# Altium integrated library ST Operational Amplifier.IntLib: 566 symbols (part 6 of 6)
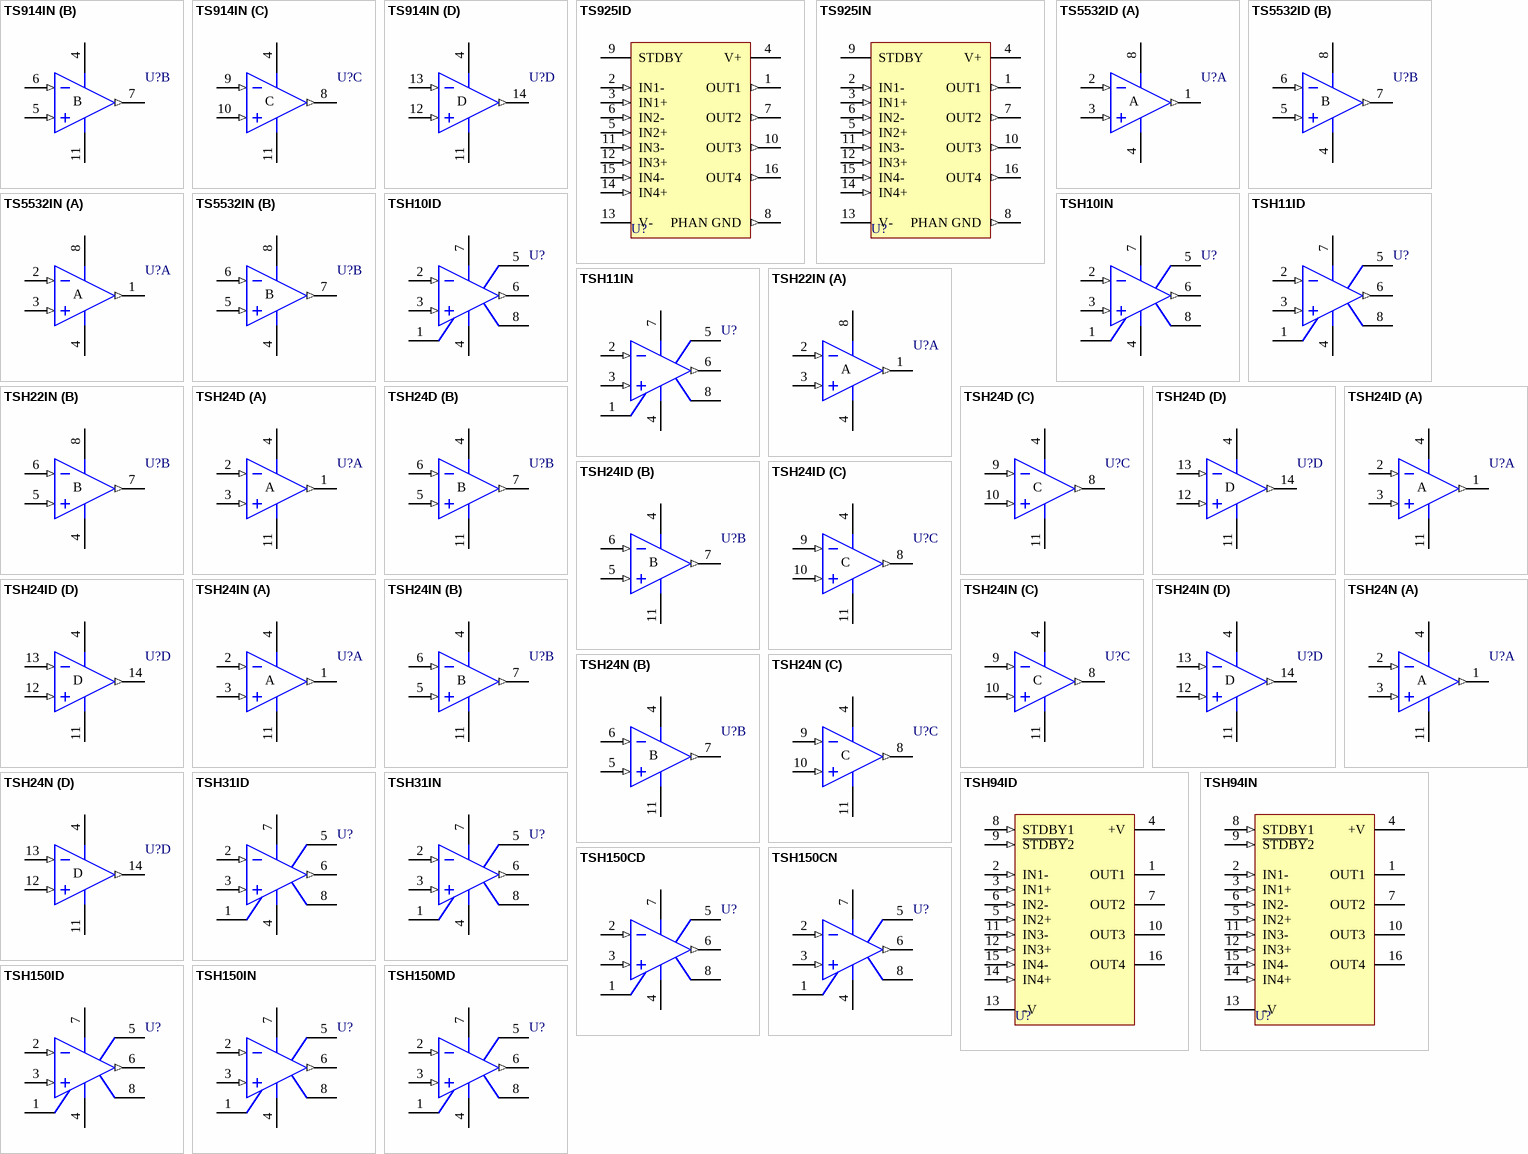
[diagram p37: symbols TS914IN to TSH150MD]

## TS925IN
designator U?
Rail-to-Rail High-Output-Current Quad Operational Amplifier
footprint DIP16 (DIP; 16 Leads; Row Spacing 7.62 mm; Pitch 2.54 mm)
3D model DIP16 (DIP; 16 Leads; Row Spacing 7.62 mm; Pitch 2.54 mm)
pins: 1 OUT1 (out), 2 IN1- (in), 3 IN1+ (in), 4 V+ (power), 5 IN2+ (in), 6 IN2- (in), 7 OUT2 (out), 8 PHAN GND (out), 9 STDBY, 10 OUT3 (out), 11 IN3- (in), 12 IN3+ (in), 13 V- (power), 14 IN4+ (in), 15 IN4- (in), 16 OUT4 (out)

## TS5532ID
designator U?
Low-Noise Dual Operational Amplifier
footprint SO8_N (SOIC, 8-Leads, Body 4.9x3.9mm, Pitch 1.27mm, IPC Medium Density)
footprint SO8_L (SOIC, 8-Leads, Body 4.9x3.9mm, Pitch 1.27mm, IPC High Density)
footprint SO8_M (SOIC, 8-Leads, Body 4.9x3.9mm, Pitch 1.27mm, IPC Low Density)
3D model SO8 (8-Pin Small Outline Integrated Circuit 1.27 mm Pitch)
pins on every part: 4 V- (power), 8 V+ (power)
part A pins: 1 OUT (out), 2 IN- (in), 3 IN+ (in)
part B pins: 5 IN+ (in), 6 IN- (in), 7 OUT (out)

## TS5532IN
designator U?
Low-Noise Dual Operational Amplifier
footprint DIP8 (DIP; 8 Leads; Row Spacing 7.62 mm; Pitch 2.54 mm)
3D model DIP8 (DIP; 8 Leads; Row Spacing 7.62 mm; Pitch 2.54 mm)
pins on every part: 4 V- (power), 8 V+ (power)
part A pins: 1 OUT (out), 2 IN- (in), 3 IN+ (in)
part B pins: 5 IN+ (in), 6 IN- (in), 7 OUT (out)

## TSH10ID
designator U?
140MHz Bandwidth Low-Noise Operational Amplifier; Note: Pins 5 is Not Connected
footprint SO8_N (SOIC, 8-Leads, Body 4.9x3.9mm, Pitch 1.27mm, IPC Medium Density)
footprint SO8_L (SOIC, 8-Leads, Body 4.9x3.9mm, Pitch 1.27mm, IPC High Density)
footprint SO8_M (SOIC, 8-Leads, Body 4.9x3.9mm, Pitch 1.27mm, IPC Low Density)
3D model SO8 (8-Pin Small Outline Integrated Circuit 1.27 mm Pitch)
pins: 1 NULL1, 2 IN- (in), 3 IN+ (in), 4 V- (power), 5 NC, 6 OUT (out), 7 V+ (power), 8 NULL2

## TSH10IN
designator U?
140MHz Bandwidth Low-Noise Operational Amplifier; Note: Pins 5 is Not Connected
footprint DIP8 (DIP; 8 Leads; Row Spacing 7.62 mm; Pitch 2.54 mm)
3D model DIP8 (DIP; 8 Leads; Row Spacing 7.62 mm; Pitch 2.54 mm)
pins: 1 NULL1, 2 IN- (in), 3 IN+ (in), 4 V- (power), 5 NC, 6 OUT (out), 7 V+ (power), 8 NULL2

## TSH11ID
designator U?
120MHz Bandwidth MOS Input Single Operational Amplifier; Note: Pins 5 is Not Connected
footprint SO8_N (SOIC, 8-Leads, Body 4.9x3.9mm, Pitch 1.27mm, IPC Medium Density)
footprint SO8_L (SOIC, 8-Leads, Body 4.9x3.9mm, Pitch 1.27mm, IPC High Density)
footprint SO8_M (SOIC, 8-Leads, Body 4.9x3.9mm, Pitch 1.27mm, IPC Low Density)
3D model SO8 (8-Pin Small Outline Integrated Circuit 1.27 mm Pitch)
pins: 1 NULL1, 2 IN- (in), 3 IN+ (in), 4 V- (power), 5 NC, 6 OUT (out), 7 V+ (power), 8 NULL2

## TSH11IN
designator U?
120MHz Bandwidth MOS Input Single Operational Amplifier; Note: Pins 5 is Not Connected
footprint DIP8 (DIP; 8 Leads; Row Spacing 7.62 mm; Pitch 2.54 mm)
3D model DIP8 (DIP; 8 Leads; Row Spacing 7.62 mm; Pitch 2.54 mm)
pins: 1 NULL1, 2 IN- (in), 3 IN+ (in), 4 V- (power), 5 NC, 6 OUT (out), 7 V+ (power), 8 NULL2

## TSH22IN
designator U?
High-Performance Dual Bipolar Operational Amplifier
footprint DIP8 (DIP; 8 Leads; Row Spacing 7.62 mm; Pitch 2.54 mm)
3D model DIP8 (DIP; 8 Leads; Row Spacing 7.62 mm; Pitch 2.54 mm)
pins on every part: 4 V- (power), 8 V+ (power)
part A pins: 1 OUT (out), 2 IN- (in), 3 IN+ (in)
part B pins: 5 IN+ (in), 6 IN- (in), 7 OUT (out)

## TSH24D
designator U?
High-Performance Quad Bipolar Operational Amplifier
footprint SO14_N (SOIC, 14-Leads, Body 8.7x3.9mm, Pitch 1.27mm, IPC Medium Density)
footprint SO14_L (SOIC, 14-Leads, Body 8.7x3.9mm, Pitch 1.27mm, IPC High Density)
footprint SO14_M (SOIC, 14-Leads, Body 8.7x3.9mm, Pitch 1.27mm, IPC Low Density)
3D model SO14 (14-Pin Small Outline Integrated Circuit 1.27 mm Pitch)
pins on every part: 4 V+ (power), 11 V- (power)
part A pins: 1 OUT (out), 2 IN- (in), 3 IN+ (in)
part B pins: 5 IN+ (in), 6 IN- (in), 7 OUT (out)
part C pins: 8 OUT (out), 9 IN- (in), 10 IN+ (in)
part D pins: 12 IN+ (in), 13 IN- (in), 14 OUT (out)

## TSH24ID
designator U?
High-Performance Quad Bipolar Operational Amplifier
footprint SO14_N (SOIC, 14-Leads, Body 8.7x3.9mm, Pitch 1.27mm, IPC Medium Density)
footprint SO14_L (SOIC, 14-Leads, Body 8.7x3.9mm, Pitch 1.27mm, IPC High Density)
footprint SO14_M (SOIC, 14-Leads, Body 8.7x3.9mm, Pitch 1.27mm, IPC Low Density)
3D model SO14 (14-Pin Small Outline Integrated Circuit 1.27 mm Pitch)
pins on every part: 4 V+ (power), 11 V- (power)
part A pins: 1 OUT (out), 2 IN- (in), 3 IN+ (in)
part B pins: 5 IN+ (in), 6 IN- (in), 7 OUT (out)
part C pins: 8 OUT (out), 9 IN- (in), 10 IN+ (in)
part D pins: 12 IN+ (in), 13 IN- (in), 14 OUT (out)

## TSH24IN
designator U?
High-Performance Quad Bipolar Operational Amplifier
footprint DIP14 (DIP; 14 Leads; Row Spacing 7.62 mm; Pitch 2.54 mm)
3D model DIP14 (DIP; 14 Leads; Row Spacing 7.62 mm; Pitch 2.54 mm)
pins on every part: 4 V+ (power), 11 V- (power)
part A pins: 1 OUT (out), 2 IN- (in), 3 IN+ (in)
part B pins: 5 IN+ (in), 6 IN- (in), 7 OUT (out)
part C pins: 8 OUT (out), 9 IN- (in), 10 IN+ (in)
part D pins: 12 IN+ (in), 13 IN- (in), 14 OUT (out)

## TSH24N
designator U?
High-Performance Quad Bipolar Operational Amplifier
footprint DIP14 (DIP; 14 Leads; Row Spacing 7.62 mm; Pitch 2.54 mm)
3D model DIP14 (DIP; 14 Leads; Row Spacing 7.62 mm; Pitch 2.54 mm)
pins on every part: 4 V+ (power), 11 V- (power)
part A pins: 1 OUT (out), 2 IN- (in), 3 IN+ (in)
part B pins: 5 IN+ (in), 6 IN- (in), 7 OUT (out)
part C pins: 8 OUT (out), 9 IN- (in), 10 IN+ (in)
part D pins: 12 IN+ (in), 13 IN- (in), 14 OUT (out)

## TSH31ID
designator U?
280MHz Bandwidth MOS Input Single Operational Amplifier; Note: Pins 5 is Not Connected
footprint SO8_N (SOIC, 8-Leads, Body 4.9x3.9mm, Pitch 1.27mm, IPC Medium Density)
footprint SO8_L (SOIC, 8-Leads, Body 4.9x3.9mm, Pitch 1.27mm, IPC High Density)
footprint SO8_M (SOIC, 8-Leads, Body 4.9x3.9mm, Pitch 1.27mm, IPC Low Density)
3D model SO8 (8-Pin Small Outline Integrated Circuit 1.27 mm Pitch)
pins: 1 NULL1, 2 IN- (in), 3 IN+ (in), 4 V- (power), 5 NC, 6 OUT (out), 7 V+ (power), 8 NULL2

## TSH31IN
designator U?
280MHz Bandwidth MOS Input Single Operational Amplifier; Note: Pins 5 is Not Connected
footprint DIP8 (DIP; 8 Leads; Row Spacing 7.62 mm; Pitch 2.54 mm)
3D model DIP8 (DIP; 8 Leads; Row Spacing 7.62 mm; Pitch 2.54 mm)
pins: 1 NULL1, 2 IN- (in), 3 IN+ (in), 4 V- (power), 5 NC, 6 OUT (out), 7 V+ (power), 8 NULL2

## TSH94ID
designator U?
High-Speed Low-Power Quad Operational Amplifier (with Standby Position)
footprint SO16_N (SOIC, 16-Leads, Body 9.9x3.9mm, Pitch 1.27mm, IPC Medium Density)
footprint SO16_L (SOIC, 16-Leads, Body 9.9x3.9mm, Pitch 1.27mm, IPC High Density)
footprint SO16_M (SOIC, 16-Leads, Body 9.9x3.9mm, Pitch 1.27mm, IPC Low Density)
3D model SO16 (16-Pin Small Outline Integrated Circuit 1.27 mm Pitch)
pins: 1 OUT1 (hiz), 2 IN1- (in), 3 IN1+ (in), 4 +V (power), 5 IN2+ (in), 6 IN2- (in), 7 OUT2 (hiz), 8 STDBY1 (in), 9 ~{STDBY}2 (in), 10 OUT3 (hiz), 11 IN3- (in), 12 IN3+ (in), 13 -V (power), 14 IN4+ (in), 15 IN4- (in), 16 OUT4 (hiz)

## TSH94IN
designator U?
High-Speed Low-Power Quad Operational Amplifier (with Standby Position)
footprint DIP16 (DIP; 16 Leads; Row Spacing 7.62 mm; Pitch 2.54 mm)
3D model DIP16 (DIP; 16 Leads; Row Spacing 7.62 mm; Pitch 2.54 mm)
pins: 1 OUT1 (hiz), 2 IN1- (in), 3 IN1+ (in), 4 +V (power), 5 IN2+ (in), 6 IN2- (in), 7 OUT2 (hiz), 8 STDBY1 (in), 9 ~{STDBY}2 (in), 10 OUT3 (hiz), 11 IN3- (in), 12 IN3+ (in), 13 -V (power), 14 IN4+ (in), 15 IN4- (in), 16 OUT4 (hiz)

## TSH150CD
designator U?
Wide-Bandwidth and Bipolar Inputs Single Operational Amplifier; Note: Pins 5 is Not Connected
footprint SO8_N (SOIC, 8-Leads, Body 4.9x3.9mm, Pitch 1.27mm, IPC Medium Density)
footprint SO8_L (SOIC, 8-Leads, Body 4.9x3.9mm, Pitch 1.27mm, IPC High Density)
footprint SO8_M (SOIC, 8-Leads, Body 4.9x3.9mm, Pitch 1.27mm, IPC Low Density)
3D model SO8 (8-Pin Small Outline Integrated Circuit 1.27 mm Pitch)
pins: 1 NULL1, 2 IN- (in), 3 IN+ (in), 4 V- (power), 5 NC, 6 OUT (out), 7 V+ (power), 8 NULL2

## TSH150CN
designator U?
Wide-Bandwidth and Bipolar Inputs Single Operational Amplifier; Note: Pins 5 is Not Connected
footprint DIP8 (DIP; 8 Leads; Row Spacing 7.62 mm; Pitch 2.54 mm)
3D model DIP8 (DIP; 8 Leads; Row Spacing 7.62 mm; Pitch 2.54 mm)
pins: 1 NULL1, 2 IN- (in), 3 IN+ (in), 4 V- (power), 5 NC, 6 OUT (out), 7 V+ (power), 8 NULL2

## TSH150ID
designator U?
Wide-Bandwidth and Bipolar Inputs Single Operational Amplifier; Note: Pins 5 is Not Connected
footprint SO8_N (SOIC, 8-Leads, Body 4.9x3.9mm, Pitch 1.27mm, IPC Medium Density)
footprint SO8_L (SOIC, 8-Leads, Body 4.9x3.9mm, Pitch 1.27mm, IPC High Density)
footprint SO8_M (SOIC, 8-Leads, Body 4.9x3.9mm, Pitch 1.27mm, IPC Low Density)
3D model SO8 (8-Pin Small Outline Integrated Circuit 1.27 mm Pitch)
pins: 1 NULL1, 2 IN- (in), 3 IN+ (in), 4 V- (power), 5 NC, 6 OUT (out), 7 V+ (power), 8 NULL2

## TSH150IN
designator U?
Wide-Bandwidth and Bipolar Inputs Single Operational Amplifier; Note: Pins 5 is Not Connected
footprint DIP8 (DIP; 8 Leads; Row Spacing 7.62 mm; Pitch 2.54 mm)
3D model DIP8 (DIP; 8 Leads; Row Spacing 7.62 mm; Pitch 2.54 mm)
pins: 1 NULL1, 2 IN- (in), 3 IN+ (in), 4 V- (power), 5 NC, 6 OUT (out), 7 V+ (power), 8 NULL2

## TSH150MD
designator U?
Wide-Bandwidth and Bipolar Inputs Single Operational Amplifier; Note: Pins 5 is Not Connected
footprint SO8_N (SOIC, 8-Leads, Body 4.9x3.9mm, Pitch 1.27mm, IPC Medium Density)
footprint SO8_L (SOIC, 8-Leads, Body 4.9x3.9mm, Pitch 1.27mm, IPC High Density)
footprint SO8_M (SOIC, 8-Leads, Body 4.9x3.9mm, Pitch 1.27mm, IPC Low Density)
3D model SO8 (8-Pin Small Outline Integrated Circuit 1.27 mm Pitch)
pins: 1 NULL1, 2 IN- (in), 3 IN+ (in), 4 V- (power), 5 NC, 6 OUT (out), 7 V+ (power), 8 NULL2

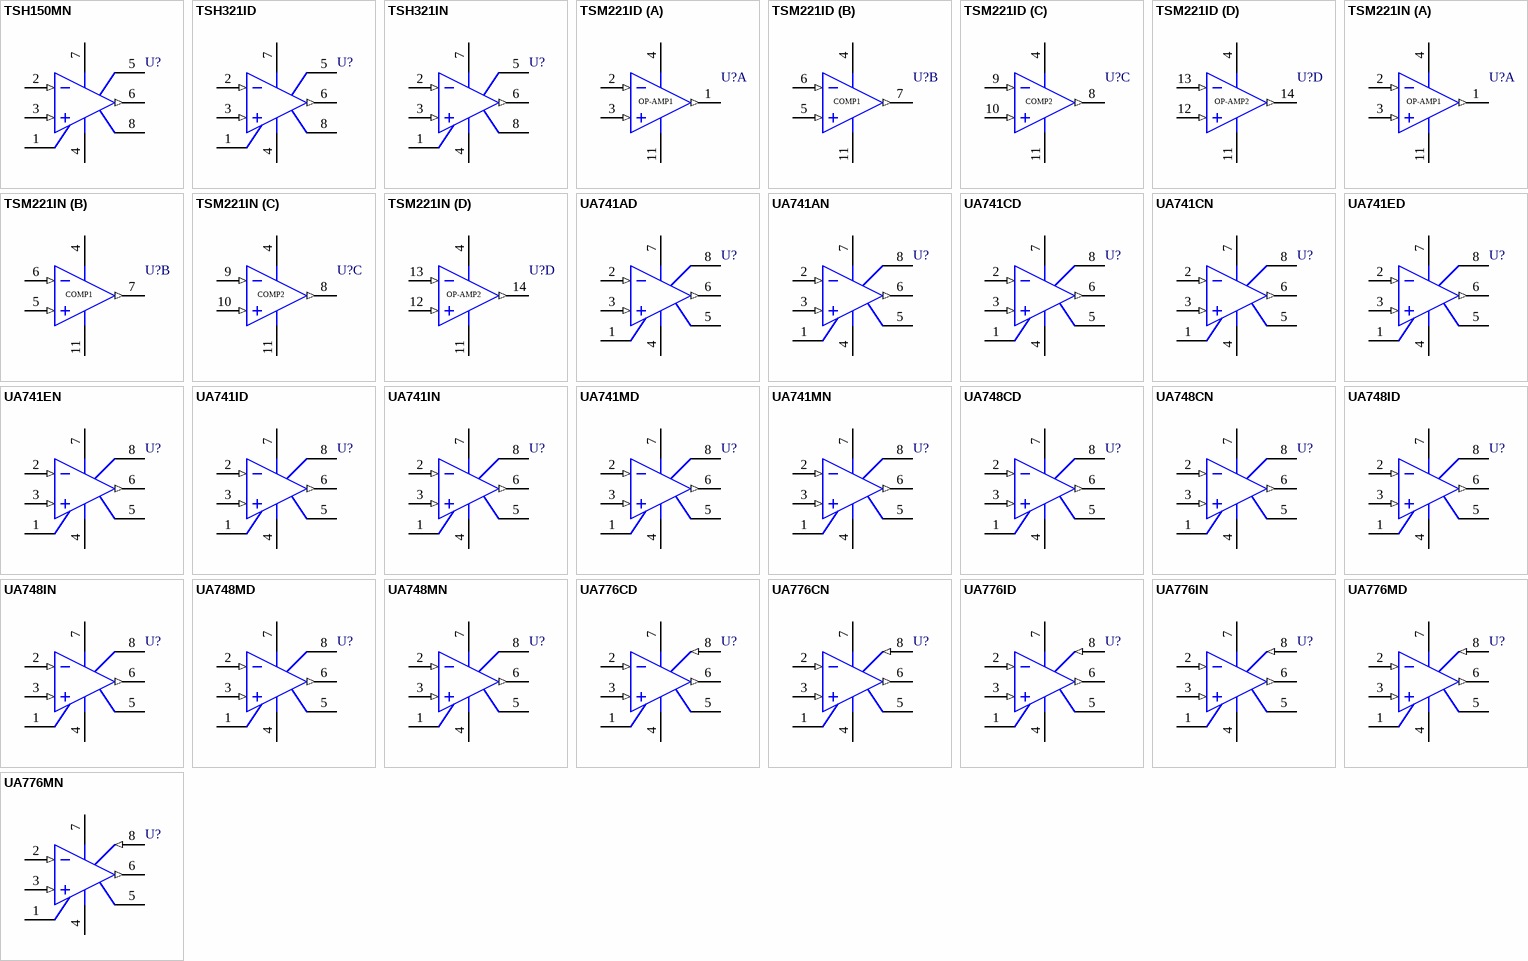
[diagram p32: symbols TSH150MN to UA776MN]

## TSH150MN
designator U?
Wide-Bandwidth and Bipolar Inputs Single Operational Amplifier; Note: Pins 5 is Not Connected
footprint DIP8 (DIP; 8 Leads; Row Spacing 7.62 mm; Pitch 2.54 mm)
3D model DIP8 (DIP; 8 Leads; Row Spacing 7.62 mm; Pitch 2.54 mm)
pins: 1 NULL1, 2 IN- (in), 3 IN+ (in), 4 V- (power), 5 NC, 6 OUT (out), 7 V+ (power), 8 NULL2

## TSH321ID
designator U?
Wide-Bandwidth and MOS Inputs Single Operational Amplifier; Note: Pins 5 is Not Connected
footprint SO8_N (SOIC, 8-Leads, Body 4.9x3.9mm, Pitch 1.27mm, IPC Medium Density)
footprint SO8_L (SOIC, 8-Leads, Body 4.9x3.9mm, Pitch 1.27mm, IPC High Density)
footprint SO8_M (SOIC, 8-Leads, Body 4.9x3.9mm, Pitch 1.27mm, IPC Low Density)
3D model SO8 (8-Pin Small Outline Integrated Circuit 1.27 mm Pitch)
pins: 1 NULL1, 2 IN- (in), 3 IN+ (in), 4 V- (power), 5 NC, 6 OUT (out), 7 V+ (power), 8 NULL2

## TSH321IN
designator U?
Wide-Bandwidth and MOS Inputs Single Operational Amplifier; Note: Pins 5 is Not Connected
footprint DIP8 (DIP; 8 Leads; Row Spacing 7.62 mm; Pitch 2.54 mm)
3D model DIP8 (DIP; 8 Leads; Row Spacing 7.62 mm; Pitch 2.54 mm)
pins: 1 NULL1, 2 IN- (in), 3 IN+ (in), 4 V- (power), 5 NC, 6 OUT (out), 7 V+ (power), 8 NULL2

## TSM221ID
designator U?
Dual CMOS Rail-to-Rail Operational Amplifier and Dual CMOS Comparator; ComponentAvailability: Not for New Design
footprint SO14_N (SOIC, 14-Leads, Body 8.7x3.9mm, Pitch 1.27mm, IPC Medium Density)
footprint SO14_L (SOIC, 14-Leads, Body 8.7x3.9mm, Pitch 1.27mm, IPC High Density)
footprint SO14_M (SOIC, 14-Leads, Body 8.7x3.9mm, Pitch 1.27mm, IPC Low Density)
3D model SO14 (14-Pin Small Outline Integrated Circuit 1.27 mm Pitch)
pins on every part: 4 V+ (power), 11 V- (power)
part A pins: 1 OUT (out), 2 IN- (in), 3 IN+ (in)
part B pins: 5 IN+ (in), 6 IN- (in), 7 OUT (out)
part C pins: 8 OUT (out), 9 IN- (in), 10 IN+ (in)
part D pins: 12 IN+ (in), 13 IN- (in), 14 OUT (out)

## TSM221IN
designator U?
Dual CMOS Rail-to-Rail Operational Amplifier and Dual CMOS Comparator; ComponentAvailability: Not for New Design
footprint DIP14 (DIP; 14 Leads; Row Spacing 7.62 mm; Pitch 2.54 mm)
3D model DIP14 (DIP; 14 Leads; Row Spacing 7.62 mm; Pitch 2.54 mm)
pins on every part: 4 V+ (power), 11 V- (power)
part A pins: 1 OUT (out), 2 IN- (in), 3 IN+ (in)
part B pins: 5 IN+ (in), 6 IN- (in), 7 OUT (out)
part C pins: 8 OUT (out), 9 IN- (in), 10 IN+ (in)
part D pins: 12 IN+ (in), 13 IN- (in), 14 OUT (out)

## UA741AD
designator U?
General-Purpose Single Operational Amplifier
footprint SO8_N (SOIC, 8-Leads, Body 4.9x3.9mm, Pitch 1.27mm, IPC Medium Density)
footprint SO8_L (SOIC, 8-Leads, Body 4.9x3.9mm, Pitch 1.27mm, IPC High Density)
footprint SO8_M (SOIC, 8-Leads, Body 4.9x3.9mm, Pitch 1.27mm, IPC Low Density)
3D model SO8 (8-Pin Small Outline Integrated Circuit 1.27 mm Pitch)
simulation model UA741 (SUBCKT)
pins: 1 OS NULL, 2 IN- (in), 3 IN+ (in), 4 V- (power), 5 OS NULL, 6 OUT (out), 7 V+ (power), 8 NC

## UA741AN
designator U?
General-Purpose Single Operational Amplifier
footprint DIP8 (DIP; 8 Leads; Row Spacing 7.62 mm; Pitch 2.54 mm)
3D model DIP8 (DIP; 8 Leads; Row Spacing 7.62 mm; Pitch 2.54 mm)
simulation model UA741 (SUBCKT)
pins: 1 OS NULL, 2 IN- (in), 3 IN+ (in), 4 V- (power), 5 OS NULL, 6 OUT (out), 7 V+ (power), 8 NC

## UA741CD
designator U?
General-Purpose Single Operational Amplifier
footprint SO8_N (SOIC, 8-Leads, Body 4.9x3.9mm, Pitch 1.27mm, IPC Medium Density)
footprint SO8_L (SOIC, 8-Leads, Body 4.9x3.9mm, Pitch 1.27mm, IPC High Density)
footprint SO8_M (SOIC, 8-Leads, Body 4.9x3.9mm, Pitch 1.27mm, IPC Low Density)
3D model SO8 (8-Pin Small Outline Integrated Circuit 1.27 mm Pitch)
simulation model UA741 (SUBCKT)
pins: 1 OS NULL, 2 IN- (in), 3 IN+ (in), 4 V- (power), 5 OS NULL, 6 OUT (out), 7 V+ (power), 8 NC

## UA741CN
designator U?
General-Purpose Single Operational Amplifier
footprint DIP8 (DIP; 8 Leads; Row Spacing 7.62 mm; Pitch 2.54 mm)
3D model DIP8 (DIP; 8 Leads; Row Spacing 7.62 mm; Pitch 2.54 mm)
simulation model UA741 (SUBCKT)
pins: 1 OS NULL, 2 IN- (in), 3 IN+ (in), 4 V- (power), 5 OS NULL, 6 OUT (out), 7 V+ (power), 8 NC

## UA741ED
designator U?
General-Purpose Single Operational Amplifier
footprint SO8_N (SOIC, 8-Leads, Body 4.9x3.9mm, Pitch 1.27mm, IPC Medium Density)
footprint SO8_L (SOIC, 8-Leads, Body 4.9x3.9mm, Pitch 1.27mm, IPC High Density)
footprint SO8_M (SOIC, 8-Leads, Body 4.9x3.9mm, Pitch 1.27mm, IPC Low Density)
3D model SO8 (8-Pin Small Outline Integrated Circuit 1.27 mm Pitch)
simulation model UA741 (SUBCKT)
pins: 1 OS NULL, 2 IN- (in), 3 IN+ (in), 4 V- (power), 5 OS NULL, 6 OUT (out), 7 V+ (power), 8 NC

## UA741EN
designator U?
General-Purpose Single Operational Amplifier
footprint DIP8 (DIP; 8 Leads; Row Spacing 7.62 mm; Pitch 2.54 mm)
3D model DIP8 (DIP; 8 Leads; Row Spacing 7.62 mm; Pitch 2.54 mm)
simulation model UA741 (SUBCKT)
pins: 1 OS NULL, 2 IN- (in), 3 IN+ (in), 4 V- (power), 5 OS NULL, 6 OUT (out), 7 V+ (power), 8 NC

## UA741ID
designator U?
General-Purpose Single Operational Amplifier
footprint SO8_N (SOIC, 8-Leads, Body 4.9x3.9mm, Pitch 1.27mm, IPC Medium Density)
footprint SO8_L (SOIC, 8-Leads, Body 4.9x3.9mm, Pitch 1.27mm, IPC High Density)
footprint SO8_M (SOIC, 8-Leads, Body 4.9x3.9mm, Pitch 1.27mm, IPC Low Density)
3D model SO8 (8-Pin Small Outline Integrated Circuit 1.27 mm Pitch)
simulation model UA741 (SUBCKT)
pins: 1 OS NULL, 2 IN- (in), 3 IN+ (in), 4 V- (power), 5 OS NULL, 6 OUT (out), 7 V+ (power), 8 NC

## UA741IN
designator U?
General-Purpose Single Operational Amplifier
footprint DIP8 (DIP; 8 Leads; Row Spacing 7.62 mm; Pitch 2.54 mm)
3D model DIP8 (DIP; 8 Leads; Row Spacing 7.62 mm; Pitch 2.54 mm)
simulation model UA741 (SUBCKT)
pins: 1 OS NULL, 2 IN- (in), 3 IN+ (in), 4 V- (power), 5 OS NULL, 6 OUT (out), 7 V+ (power), 8 NC

## UA741MD
designator U?
General-Purpose Single Operational Amplifier
footprint SO8_N (SOIC, 8-Leads, Body 4.9x3.9mm, Pitch 1.27mm, IPC Medium Density)
footprint SO8_L (SOIC, 8-Leads, Body 4.9x3.9mm, Pitch 1.27mm, IPC High Density)
footprint SO8_M (SOIC, 8-Leads, Body 4.9x3.9mm, Pitch 1.27mm, IPC Low Density)
3D model SO8 (8-Pin Small Outline Integrated Circuit 1.27 mm Pitch)
simulation model UA741 (SUBCKT)
pins: 1 OS NULL, 2 IN- (in), 3 IN+ (in), 4 V- (power), 5 OS NULL, 6 OUT (out), 7 V+ (power), 8 NC

## UA741MN
designator U?
General-Purpose Single Operational Amplifier
footprint DIP8 (DIP; 8 Leads; Row Spacing 7.62 mm; Pitch 2.54 mm)
3D model DIP8 (DIP; 8 Leads; Row Spacing 7.62 mm; Pitch 2.54 mm)
simulation model UA741 (SUBCKT)
pins: 1 OS NULL, 2 IN- (in), 3 IN+ (in), 4 V- (power), 5 OS NULL, 6 OUT (out), 7 V+ (power), 8 NC

## UA748CD
designator U?
Precision Single Operational Amplifier
footprint SO8_N (SOIC, 8-Leads, Body 4.9x3.9mm, Pitch 1.27mm, IPC Medium Density)
footprint SO8_L (SOIC, 8-Leads, Body 4.9x3.9mm, Pitch 1.27mm, IPC High Density)
footprint SO8_M (SOIC, 8-Leads, Body 4.9x3.9mm, Pitch 1.27mm, IPC Low Density)
3D model SO8 (8-Pin Small Outline Integrated Circuit 1.27 mm Pitch)
simulation model UA748 (SUBCKT)
pins: 1 OS NULL1/FCOMP, 2 IN- (in), 3 IN+ (in), 4 V- (power), 5 OS NULL2, 6 OUT (out), 7 V+ (power), 8 FCOMP

## UA748CN
designator U?
Precision Single Operational Amplifier
footprint DIP8 (DIP; 8 Leads; Row Spacing 7.62 mm; Pitch 2.54 mm)
3D model DIP8 (DIP; 8 Leads; Row Spacing 7.62 mm; Pitch 2.54 mm)
simulation model UA748 (SUBCKT)
pins: 1 OS NULL1/FCOMP, 2 IN- (in), 3 IN+ (in), 4 V- (power), 5 OS NULL2, 6 OUT (out), 7 V+ (power), 8 FCOMP

## UA748ID
designator U?
Precision Single Operational Amplifier
footprint SO8_N (SOIC, 8-Leads, Body 4.9x3.9mm, Pitch 1.27mm, IPC Medium Density)
footprint SO8_L (SOIC, 8-Leads, Body 4.9x3.9mm, Pitch 1.27mm, IPC High Density)
footprint SO8_M (SOIC, 8-Leads, Body 4.9x3.9mm, Pitch 1.27mm, IPC Low Density)
3D model SO8 (8-Pin Small Outline Integrated Circuit 1.27 mm Pitch)
simulation model UA748 (SUBCKT)
pins: 1 OS NULL1/FCOMP, 2 IN- (in), 3 IN+ (in), 4 V- (power), 5 OS NULL2, 6 OUT (out), 7 V+ (power), 8 FCOMP

## UA748IN
designator U?
Precision Single Operational Amplifier
footprint DIP8 (DIP; 8 Leads; Row Spacing 7.62 mm; Pitch 2.54 mm)
3D model DIP8 (DIP; 8 Leads; Row Spacing 7.62 mm; Pitch 2.54 mm)
simulation model UA748 (SUBCKT)
pins: 1 OS NULL1/FCOMP, 2 IN- (in), 3 IN+ (in), 4 V- (power), 5 OS NULL2, 6 OUT (out), 7 V+ (power), 8 FCOMP

## UA748MD
designator U?
Precision Single Operational Amplifier
footprint SO8_N (SOIC, 8-Leads, Body 4.9x3.9mm, Pitch 1.27mm, IPC Medium Density)
footprint SO8_L (SOIC, 8-Leads, Body 4.9x3.9mm, Pitch 1.27mm, IPC High Density)
footprint SO8_M (SOIC, 8-Leads, Body 4.9x3.9mm, Pitch 1.27mm, IPC Low Density)
3D model SO8 (8-Pin Small Outline Integrated Circuit 1.27 mm Pitch)
simulation model UA748 (SUBCKT)
pins: 1 OS NULL1/FCOMP, 2 IN- (in), 3 IN+ (in), 4 V- (power), 5 OS NULL2, 6 OUT (out), 7 V+ (power), 8 FCOMP

## UA748MN
designator U?
Precision Single Operational Amplifier
footprint DIP8 (DIP; 8 Leads; Row Spacing 7.62 mm; Pitch 2.54 mm)
3D model DIP8 (DIP; 8 Leads; Row Spacing 7.62 mm; Pitch 2.54 mm)
simulation model UA748 (SUBCKT)
pins: 1 OS NULL1/FCOMP, 2 IN- (in), 3 IN+ (in), 4 V- (power), 5 OS NULL2, 6 OUT (out), 7 V+ (power), 8 FCOMP

## UA776CD
designator U?
Programmable Low-Power Single Operational Amplifier
footprint SO8_N (SOIC, 8-Leads, Body 4.9x3.9mm, Pitch 1.27mm, IPC Medium Density)
footprint SO8_L (SOIC, 8-Leads, Body 4.9x3.9mm, Pitch 1.27mm, IPC High Density)
footprint SO8_M (SOIC, 8-Leads, Body 4.9x3.9mm, Pitch 1.27mm, IPC Low Density)
3D model SO8 (8-Pin Small Outline Integrated Circuit 1.27 mm Pitch)
pins: 1 OS NULL1, 2 IN- (in), 3 IN+ (in), 4 V- (power), 5 OS NULL2, 6 OUT (out), 7 V+ (power), 8 ISET (in)

## UA776CN
designator U?
Programmable Low-Power Single Operational Amplifier
footprint DIP8 (DIP; 8 Leads; Row Spacing 7.62 mm; Pitch 2.54 mm)
3D model DIP8 (DIP; 8 Leads; Row Spacing 7.62 mm; Pitch 2.54 mm)
pins: 1 OS NULL1, 2 IN- (in), 3 IN+ (in), 4 V- (power), 5 OS NULL2, 6 OUT (out), 7 V+ (power), 8 ISET (in)

## UA776ID
designator U?
Programmable Low-Power Single Operational Amplifier
footprint SO8_N (SOIC, 8-Leads, Body 4.9x3.9mm, Pitch 1.27mm, IPC Medium Density)
footprint SO8_L (SOIC, 8-Leads, Body 4.9x3.9mm, Pitch 1.27mm, IPC High Density)
footprint SO8_M (SOIC, 8-Leads, Body 4.9x3.9mm, Pitch 1.27mm, IPC Low Density)
3D model SO8 (8-Pin Small Outline Integrated Circuit 1.27 mm Pitch)
pins: 1 OS NULL1, 2 IN- (in), 3 IN+ (in), 4 V- (power), 5 OS NULL2, 6 OUT (out), 7 V+ (power), 8 ISET (in)

## UA776IN
designator U?
Programmable Low-Power Single Operational Amplifier
footprint DIP8 (DIP; 8 Leads; Row Spacing 7.62 mm; Pitch 2.54 mm)
3D model DIP8 (DIP; 8 Leads; Row Spacing 7.62 mm; Pitch 2.54 mm)
pins: 1 OS NULL1, 2 IN- (in), 3 IN+ (in), 4 V- (power), 5 OS NULL2, 6 OUT (out), 7 V+ (power), 8 ISET (in)

## UA776MD
designator U?
Programmable Low-Power Single Operational Amplifier
footprint SO8_N (SOIC, 8-Leads, Body 4.9x3.9mm, Pitch 1.27mm, IPC Medium Density)
footprint SO8_L (SOIC, 8-Leads, Body 4.9x3.9mm, Pitch 1.27mm, IPC High Density)
footprint SO8_M (SOIC, 8-Leads, Body 4.9x3.9mm, Pitch 1.27mm, IPC Low Density)
3D model SO8 (8-Pin Small Outline Integrated Circuit 1.27 mm Pitch)
pins: 1 OS NULL1, 2 IN- (in), 3 IN+ (in), 4 V- (power), 5 OS NULL2, 6 OUT (out), 7 V+ (power), 8 ISET (in)

## UA776MN
designator U?
Programmable Low-Power Single Operational Amplifier
footprint DIP8 (DIP; 8 Leads; Row Spacing 7.62 mm; Pitch 2.54 mm)
3D model DIP8 (DIP; 8 Leads; Row Spacing 7.62 mm; Pitch 2.54 mm)
pins: 1 OS NULL1, 2 IN- (in), 3 IN+ (in), 4 V- (power), 5 OS NULL2, 6 OUT (out), 7 V+ (power), 8 ISET (in)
